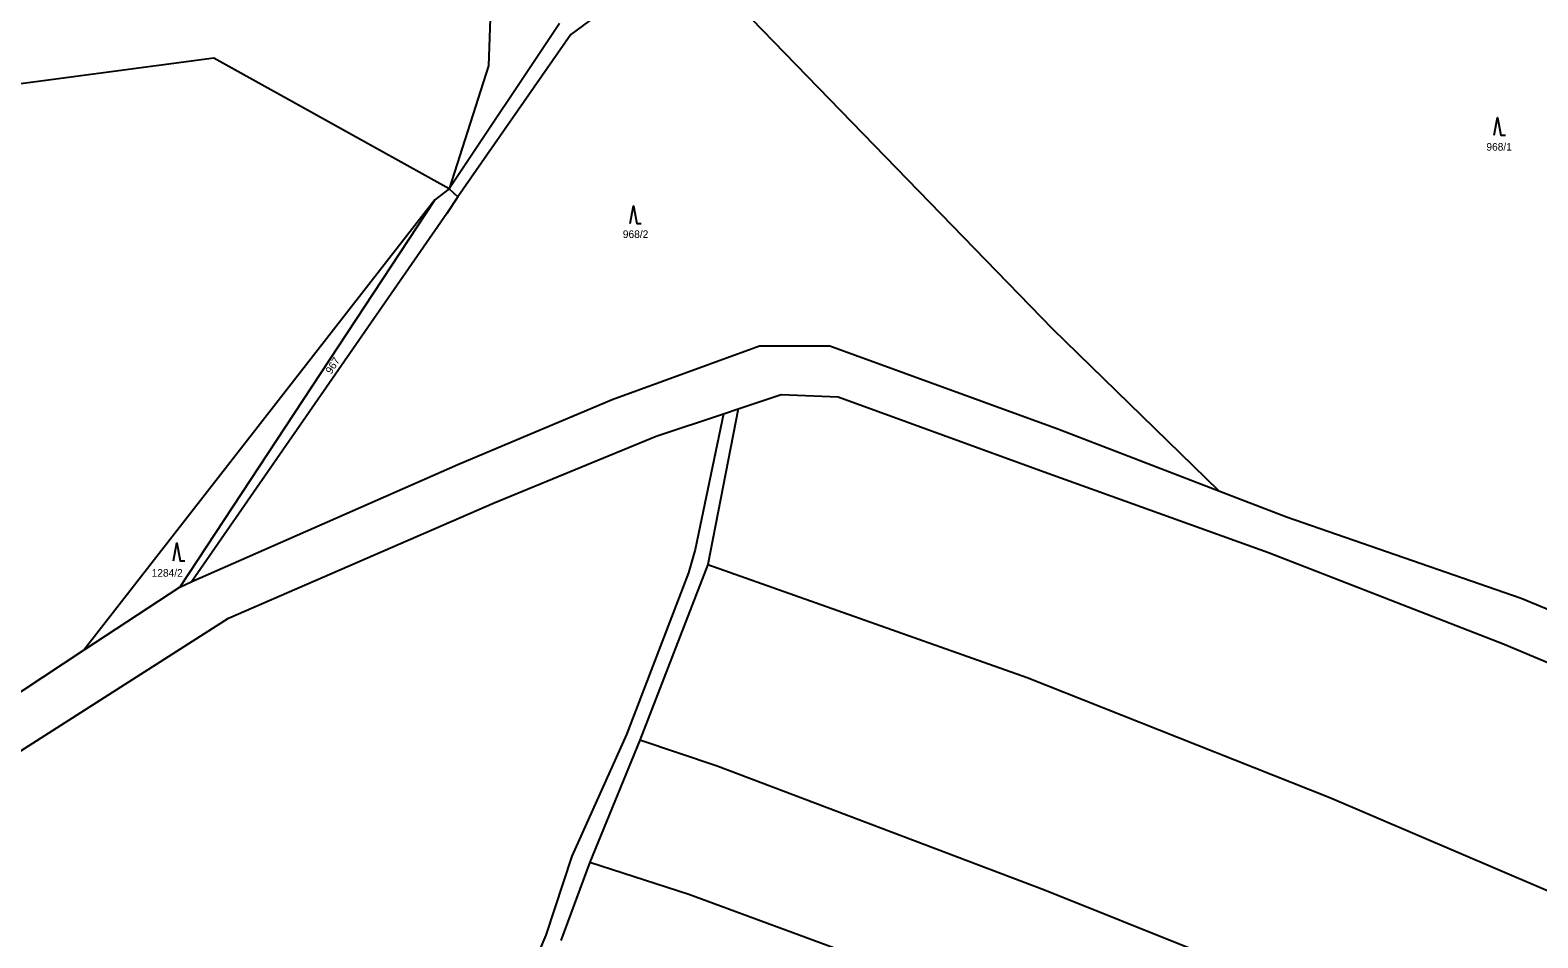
# Model space of a CAD drawing. Extents: x -779596 to -776743, y -1030330 to -1024513.
# Drawn here: x -777787 to -777450.2, y -1026665 to -1026462.1 of the extents above; entities that cross this region are included whole.
import ezdxf

# ---------------------------------------------------------------- set-up
doc = ezdxf.new("R2010")
doc.units = 0
for name, color, linetype in [('hranice parcel', 7, 'Continuous'), ('kultura', 7, 'Continuous'), ('č_parcel poz_', 7, 'Continuous')]:
    doc.layers.add(name, color=color, linetype=linetype)

msp = doc.modelspace()

# ---------------------------------------------------------------- linework, layer by layer
at = {"layer": 'hranice parcel'}
for points in [[(-777682.23, -1026402.52), (-777684.62, -1026470.11)], [(-777644.51, -1026447.01), (-777666.24, -1026463.1)], [(-777558.61, -1026528.95), (-777635.84, -1026449.23)], [(-777668.81, -1026460.59), (-777693.4, -1026497.57)], [(-777666.24, -1026463.1), (-777691.46, -1026499.4)], [(-777745.98, -1026468.33), (-777798.7, -1026475.38)], [(-777693.4, -1026497.57), (-777745.98, -1026468.33)], [(-777684.62, -1026470.11), (-777693.4, -1026497.57)], [(-777693.4, -1026497.57), (-777696.59, -1026500.01)], [(-777691.46, -1026499.4), (-777693.94, -1026503.11)], [(-777693.4, -1026497.57), (-777691.46, -1026499.4)], [(-777696.59, -1026500.01), (-777775.04, -1026600.74)], [(-777696.59, -1026500.01), (-777753.6, -1026586.6)], [(-777693.94, -1026503.11), (-777750.89, -1026585.38)], [(-777521.5, -1026565.09), (-777558.61, -1026528.95)], [(-777656.98, -1026544.66), (-777624.09, -1026532.64)], [(-777624.09, -1026532.64), (-777608.36, -1026532.66)], [(-777608.36, -1026532.66), (-777557.45, -1026551.22)], [(-777691.52, -1026559.21), (-777656.98, -1026544.66)], [(-777628.9, -1026546.78), (-777635.63, -1026581.56)], [(-777632.12, -1026547.85), (-777628.9, -1026546.78)], [(-777628.9, -1026546.78), (-777619.28, -1026543.59)], [(-777619.28, -1026543.59), (-777606.52, -1026544.09)], [(-777606.52, -1026544.09), (-777560.54, -1026560.85)], [(-777647.17, -1026552.84), (-777632.12, -1026547.85)], [(-777632.12, -1026547.85), (-777638.46, -1026578.17)], [(-777683.35, -1026567.81), (-777647.17, -1026552.84)], [(-777557.45, -1026551.22), (-777521.5, -1026565.09)], [(-777750.89, -1026585.38), (-777691.52, -1026559.21)], [(-777560.54, -1026560.85), (-777510.42, -1026578.88)], [(-777521.5, -1026565.09), (-777506.38, -1026570.93)], [(-777742.69, -1026593.57), (-777683.35, -1026567.81)], [(-777506.38, -1026570.93), (-777453.98, -1026589.11)], [(-777638.46, -1026578.17), (-777639.98, -1026583.44)], [(-777510.42, -1026578.88), (-777457.72, -1026599.34)], [(-777639.98, -1026583.44), (-777653.8, -1026619.53)], [(-777635.63, -1026581.56), (-777650.83, -1026620.8)], [(-777635.63, -1026581.56), (-777564.28, -1026606.82)], [(-777753.6, -1026586.6), (-777775.04, -1026600.74)], [(-777753.6, -1026586.6), (-777750.89, -1026585.38)], [(-777453.98, -1026589.11), (-777396.18, -1026613)], [(-777816.8, -1026640.84), (-777742.69, -1026593.57)], [(-777775.04, -1026600.74), (-777825.44, -1026634.03)], [(-777457.72, -1026599.34), (-777400.16, -1026623.62)], [(-777564.28, -1026606.82), (-777496.73, -1026633.66)], [(-777653.8, -1026619.53), (-777666, -1026646.73)], [(-777650.83, -1026620.8), (-777662.03, -1026648.12)], [(-777633.56, -1026626.67), (-777650.83, -1026620.8)], [(-777560.45, -1026654.33), (-777633.56, -1026626.67)], [(-777496.73, -1026633.66), (-777439.73, -1026658.01)], [(-777666, -1026646.73), (-777671.8, -1026664.44)], [(-777662.03, -1026648.12), (-777668.47, -1026665.62)], [(-777662.03, -1026648.12), (-777639.92, -1026655.26)], [(-777492.11, -1026681.76), (-777560.45, -1026654.33)], [(-777639.92, -1026655.26), (-777604.75, -1026668.19)], [(-777671.8, -1026664.44), (-777682.44, -1026689.48)]]:
    msp.add_lwpolyline(points, dxfattribs=at)
at = {"layer": 'kultura'}
for points in [[(-777459.97, -1026485.6), (-777459.22, -1026481.6), (-777458.47, -1026485.6), (-777457.47, -1026485.6)], [(-777653.02, -1026505.35), (-777652.27, -1026501.35), (-777651.52, -1026505.35), (-777650.52, -1026505.35)], [(-777754.99, -1026580.73), (-777754.24, -1026576.73), (-777753.49, -1026580.73), (-777752.49, -1026580.73)]]:
    msp.add_lwpolyline(points, dxfattribs=at)

# ---------------------------------------------------------------- texts
at = {"layer": 'č_parcel poz_'}
for s, p in [('968/1', (-777461.723, -1026489.04)), ('968/2', (-777654.623, -1026508.56)), ('1284/2', (-777759.889, -1026584.29))]:
    msp.add_text(s, height=1.7, dxfattribs=at).set_placement(p)
msp.add_text('967', height=1.7, rotation=57.30046, dxfattribs=at).set_placement((-777719.76, -1026539.134))

doc.saveas('drawing.dxf')
